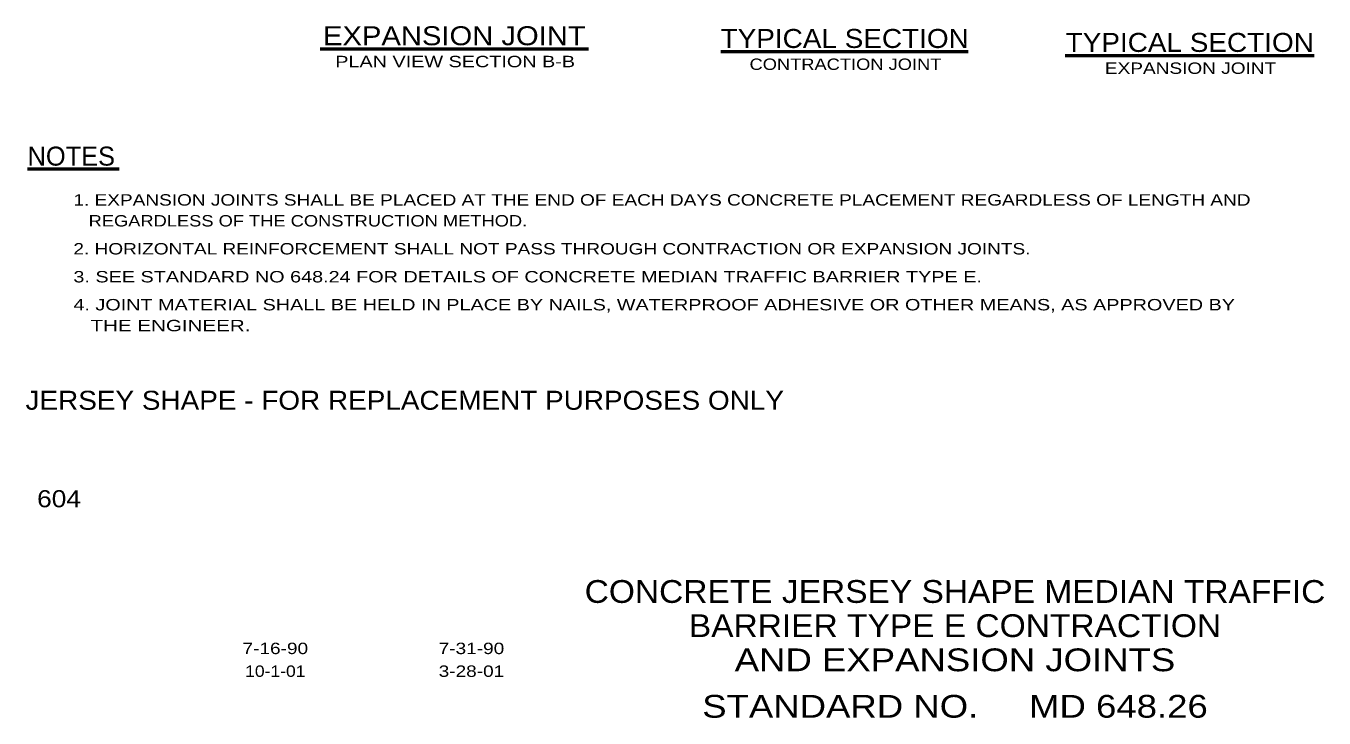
# Model space of a CAD drawing. Extents: x -43.06 to -36.2, y -1.41 to 7.25.
# Drawn here: x -43.06 to -36.22, y -1.41 to 2.23 of the extents above; entities that cross this region are included whole.
import ezdxf
from ezdxf.enums import TextEntityAlignment as Align

# ---------------------------------------------------------------- set-up
doc = ezdxf.new("R2010")
doc.units = 0
doc.header["$LTSCALE"] = 0.024
doc.layers.add('12', color=7, linetype='Continuous', lineweight=53)
doc.layers.add('13', color=7, linetype='Continuous', lineweight=53)

msp = doc.modelspace()

# ---------------------------------------------------------------- linework, layer by layer
at = {"layer": '12'}
for p, q in [((-41.50908, 2.11483), (-40.09625, 2.11483)), ((-39.39742, 2.1005), (-38.09408, 2.1005)), ((-37.58375, 2.07967), (-36.27042, 2.07967))]:
    msp.add_line(p, q, dxfattribs=at)
at = {"layer": '13'}
msp.add_line((-43.05192, 1.48233), (-42.56875, 1.48233), dxfattribs=at)

# ---------------------------------------------------------------- texts
at = {"layer": '12'}
for s, height, width, p in [('EXPANSION JOINT', 0.1, 1.15, (-40.80262, 2.1335)), ('TYPICAL SECTION', 0.1, 1.1, (-38.74558, 2.11917)), ('TYPICAL SECTION', 0.1, 1.1, (-36.92692, 2.09833)), ('PLAN VIEW SECTION B-B', 0.06001, 1.3, (-40.79838, 2.01775)), ('CONTRACTION JOINT', 0.06001, 1.2, (-38.74146, 2.00342)), ('EXPANSION JOINT', 0.06001, 1.25, (-36.92271, 1.98258))]:
    msp.add_text(s, height=height, dxfattribs=dict(at, width=width)).set_placement(p, align=Align.CENTER)
at = {"layer": '12', "width": 1.1}
msp.add_text('JERSEY SHAPE - FOR REPLACEMENT PURPOSES ONLY', height=0.1, dxfattribs=at).set_placement((-43.06267, 0.21333))
at = {"layer": '13'}
msp.add_text('NOTES', height=0.1, dxfattribs=at).set_placement((-43.05183, 1.49942))
for s, width, p in [('1. EXPANSION JOINTS SHALL BE PLACED AT THE END OF EACH DAYS CONCRETE PLACEMENT REGARDLESS OF LENGTH AND', 1.25, (-42.81033, 1.28875)), ('   REGARDLESS OF THE CONSTRUCTION METHOD.', 1.2, (-42.81033, 1.17875)), ('2. HORIZONTAL REINFORCEMENT SHALL NOT PASS THROUGH CONTRACTION OR EXPANSION JOINTS.', 1.25, (-42.81033, 1.03142)), ('3. SEE STANDARD NO 648.24 FOR DETAILS OF CONCRETE MEDIAN TRAFFIC BARRIER TYPE E.', 1.3, (-42.81033, 0.88417)), ('4. JOINT MATERIAL SHALL BE HELD IN PLACE BY NAILS, WATERPROOF ADHESIVE OR OTHER MEANS, AS APPROVED BY', 1.3, (-42.81033, 0.73683)), ('   THE ENGINEER.', 1.35, (-42.81033, 0.62683))]:
    msp.add_text(s, height=0.06001, dxfattribs=dict(at, width=width)).set_placement(p)
for s, height, width, p in [('604', 0.09001, 1.15, (-42.88604, -0.30033)), ('CONCRETE JERSEY SHAPE MEDIAN TRAFFIC', 0.12, 1.1, (-38.16421, -0.80392)), ('BARRIER TYPE E CONTRACTION', 0.12, 1.1, (-38.16421, -0.98392)), ('7-16-90', 0.06, 1.25, (-41.74625, -1.07367)), ('7-31-90', 0.06, 1.25, (-40.7125, -1.07367)), ('AND EXPANSION JOINTS', 0.12, 1.2, (-38.16421, -1.16392)), ('10-1-01', 0.06, 1.15, (-41.74625, -1.19367)), ('3-28-01', 0.06, 1.25, (-40.71254, -1.19367)), ('STANDARD NO.     MD 648.26', 0.12, 1.2, (-38.16412, -1.40875))]:
    msp.add_text(s, height=height, dxfattribs=dict(at, width=width)).set_placement(p, align=Align.CENTER)

doc.saveas('drawing.dxf')
